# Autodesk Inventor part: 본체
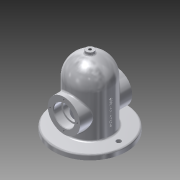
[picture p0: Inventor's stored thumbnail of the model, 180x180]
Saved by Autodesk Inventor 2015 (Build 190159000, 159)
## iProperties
Created: 2019-11
Part Number: 본체
Material: 알루미늄 6061
Document SubType Name: Modeling
Designer: now
Density: 2.7 g/cm^3
Appearance: 알루미늄 - 평지
Mass: 1089.46 g
Surface Area: 880.247 cm^2
Volume: 403.505 cm^3
Author: now
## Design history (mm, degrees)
sketch "스케치1"
  geometry: C1 r 70 at (0, 0); 1 further point
  constraints: 1 centre point, 1 coincident
  dimensions: "d0" = 140 diameter of C1
extrude "돌출1" new body sketch "스케치1" distance "d1" = 10; taper "d2" = 0 deg
sketch "스케치2"
  geometry: C1 r 70 at (0, 0) reference; C2 r 40 at (0, 0)
  constraints: 1 centre point, 1 coincident
  dimensions: "d3" = 80 diameter of C2
extrude "돌출2" join sketch "스케치2" distance "d4" = 120; taper "d5" = 0 deg
fillet "모깎기1" dims "d6" = 40
feature "쉘1" dims "d7" = 10
node "작업 평면1"
node "작업 평면2"
sketch "스케치8"
  geometry: C1 r 7.5 at (0, 0); 1 further point
  constraints: 1 centre point, 1 coincident
  dimensions: "d34" = 15 diameter of C1
extrude "돌출7" join sketch "스케치8" stored distance "d35" = 15; taper "d36" = 0 deg
sketch "스케치9"
  geometry: C1 r 7.5 at (0, 0) reference
hole "구멍2" sketch "스케치9" at (0, 0) diameter "d37" = 5.188; stored, may be unused: countersink angle "d41" = 90 deg, drill point angle "d43" = 118 deg; dims "d38" = 12, "d39" = 4, "d40" = 2, "d42" = 16
sketch "스케치10" dims "d44" = 110
  geometry: C1 r 40 at (0, 0) reference; C2 r 70 at (0, 0) reference; C3 r 4.5 at (55, 0); 2 further points
  constraints: 3 coincident, 2 horizontal alignment, 1 centre point, 2 other
  dimensions: "d45" = 9 diameter of C3
extrude "돌출8" cut sketch "스케치10" stored distance "d46" = 15; taper "d47" = 0 deg
fillet "모깎기2" dims "d48" = 3
fillet "모깎기4" dims "d50" = 3
node "작업 평면3"
sketch "스케치11"
  geometry: L1 (-70, 0)-(70, 0) reference; 3 further points
  constraints: 1 midpoint, 1 vertical alignment, 1 other
  dimensions: "d61" = 50 distance from line of L1 point (0, 50)
feature "엠보싱1" sketch "스케치11" dims "d62" = 0.5, "d63" = 0
node "작업 평면5"
  node "작업 평면4"
sketch "스케치12"
  geometry: L1 (-70, 0)-(70, 0) reference; C1 r 31 at (0, 50); 2 further points
  constraints: 1 centre point, 1 midpoint, 1 vertical alignment
  dimensions: "d66" = 62 diameter of C1; "d67" = 50 distance from line of L1 C1.centre
extrude "돌출9" join sketch "스케치12" stored distance "d68" = 15; taper "d69" = 0 deg
sketch "스케치13"
  geometry: C1 r 31 at (0, 0) reference; C2 r 20 at (0, 0); 1 further point
  constraints: 1 centre point, 1 coincident
  dimensions: "d70" = 40 diameter of C2
extrude "돌출10" cut sketch "스케치13" distance "d71" = 15; taper "d72" = 0 deg
sketch "스케치14"
  geometry: C1 r 20 at (0, 0) reference; C2 r 16.5 at (0, 0); 1 further point
  constraints: 1 centre point, 1 coincident
  dimensions: "d73" = 33 diameter of C2
extrude "돌출11" cut sketch "스케치14" stored distance "d74" = 15; taper "d75" = 0 deg
fillet "모깎기5" dims "d76" = 0.3
sketch "스케치15" dims "d77" = 52
  geometry: C1 r 20 at (0, 0) reference; C2 r 31 at (0, 0) reference; 3 further points
  constraints: 2 horizontal alignment, 1 coincident, 2 other
hole "구멍3" sketch "스케치15" at (26, 0) diameter "d78" = 3.242; stored, may be unused: countersink angle "d82" = 90 deg, drill point angle "d84" = 118 deg; dims "d79" = 8, "d80" = 4, "d81" = 2, "d83" = 10
chamfer "모따기3" distance "d88" = 1; stored, may be unused: second distance "d89" = 2, angle "d90" = 45 deg
fillet "모깎기6" dims "d91" = 0.3
fillet "모깎기7" dims "d92" = 3
fillet "모깎기8" dims "d93" = 3
node "솔리드1"
mirror "대칭4"
mirror "대칭7"
pattern_circular "원형 패턴3" dims angle "d86" = 360 deg
mirror "대칭8"
other parameters: "d33" = 135, "d64" = -5, "d65" = -45
